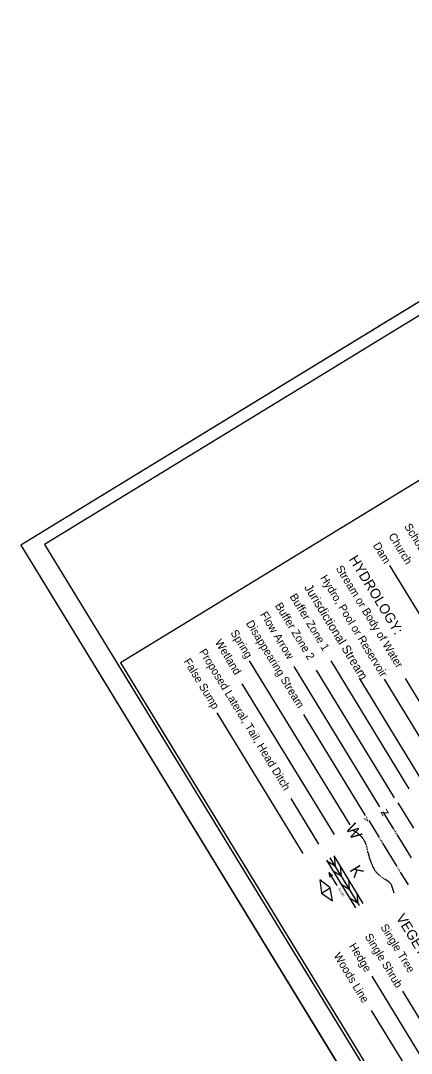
# Model space of a CAD drawing. Extents: x 1750583 to 1791140, y 783580 to 827376.
# Drawn here: x 1781915 to 1782342, y 784461 to 785591 of the extents above; entities that cross this region are included whole.
import ezdxf

# ---------------------------------------------------------------- set-up
doc = ezdxf.new("R2010")
doc.units = 0
for name, color, linetype in [('Sheet Cutting Line CELL', 7, 'Continuous'), ('Sheet Plot Border Inside CELL', 7, 'Continuous'), ('Sheet Plot Border Outside CELL', 7, 'Continuous'), ('Sheet Symbology CELL', 7, 'Continuous')]:
    doc.layers.add(name, color=color, linetype=linetype)

msp = doc.modelspace()

# ---------------------------------------------------------------- linework, layer by layer
at = {"layer": 'Sheet Cutting Line CELL'}
for p, q in [((1782853.7, 785590.6), (1781915.1, 785017.1)), ((1781915.1, 785017.1), (1782793.1, 783580.1))]:
    msp.add_line(p, q, dxfattribs=at)
at = {"layer": 'Sheet Plot Border Inside CELL'}
msp.add_lwpolyline([(1781941, 785017.7), (1782809.9, 783595.7), (1783710.2, 784145.8), (1782841.3, 785567.8)], close=True, dxfattribs=at)
at = {"layer": 'Sheet Plot Border Outside CELL'}
msp.add_lwpolyline([(1781915.1, 785017.1), (1782793.1, 783580.1), (1783731.7, 784153.6), (1782853.7, 785590.6)], close=True, dxfattribs=at)
at = {"layer": 'Sheet Symbology CELL'}
for p, q in [((1782436.3, 784802.2), (1782318.8, 784994.6)), ((1782275.2, 784711), (1782165.4, 784890.6)), ((1782339.9, 784750.5), (1782254.5, 784890.3)), ((1782307.7, 784730.9), (1782213.9, 784884.3)), ((1782323.8, 784740.7), (1782238.4, 784880.4)), ((1782258.1, 784700.6), (1782157.4, 784865.4)), ((1782354.1, 784759.2), (1782285.5, 784871.5)), ((1782373.4, 784771), (1782312.7, 784870.3)), ((1782390.4, 784781.4), (1782335.7, 784871)), ((1782224, 784679.7), (1782130, 784833.5)), ((1782292.2, 784721.4), (1782224.7, 784831.9)), ((1782241, 784690.1), (1782210.7, 784739.8)), ((1782327.5, 784735.3), (1782344.6, 784707.3)), ((1782311.1, 784725.3), (1782322.6, 784706.5)), ((1782295.6, 784715.9), (1782307.1, 784697.1)), ((1782307.6, 784696.2), (1782308.2, 784695.4)), ((1782323.1, 784705.7), (1782323.6, 784704.8)), ((1782324.1, 784704), (1782324.7, 784703.1)), ((1782325.2, 784702.2), (1782325.7, 784701.4)), ((1782326.2, 784700.5), (1782341.9, 784674.9)), ((1782293.8, 784684.3), (1782294, 784683.3)), ((1782308.7, 784694.5), (1782309.2, 784693.7)), ((1782309.7, 784692.8), (1782310.2, 784691.9)), ((1782310.8, 784691.1), (1782326.4, 784665.5)), ((1782249.3, 784672.4), (1782281.1, 784620.3)), ((1782253.1, 784675), (1782285.1, 784622.7)), ((1782257.4, 784677.3), (1782289.2, 784625.2)), ((1782257.9, 784676.5), (1782258.9, 784665.7)), ((1782258.9, 784665.7), (1782249.9, 784671.4)), ((1782264.5, 784665.7), (1782265.5, 784654.8)), ((1782326.9, 784664.6), (1782327.4, 784663.8)), ((1782328, 784662.9), (1782328.5, 784662.1)), ((1782329, 784661.2), (1782329.5, 784660.4)), ((1782253.5, 784642.1), (1782242, 784650.9)), ((1782242, 784650.9), (1782244.1, 784636.3)), ((1782252.1, 784659.1), (1782260.8, 784644.9)), ((1782252.1, 784659.1), (1782255.8, 784655.7)), ((1782252.1, 784659.1), (1782253, 784654)), ((1782265.5, 784654.8), (1782256.6, 784660.5)), ((1782273.3, 784651.2), (1782274.3, 784640.3)), ((1782308.1, 784655.3), (1782308.9, 784654.7)), ((1782309.7, 784654), (1782310.5, 784653.5)), ((1782330.1, 784659.5), (1782338.6, 784645.5)), ((1782244.1, 784636.3), (1782253.5, 784642.1)), ((1782255.8, 784627.8), (1782253.5, 784642.1)), ((1782274.3, 784640.3), (1782265.4, 784646)), ((1782244.1, 784636.3), (1782255.8, 784627.8)), ((1782283.5, 784625.4), (1782274.6, 784630.9)), ((1782282.6, 784636.1), (1782283.5, 784625.4)), ((1782410.2, 784364), (1782299.3, 784545.5)), ((1782427.3, 784374.5), (1782332.8, 784529)), ((1782393.1, 784353.6), (1782298.7, 784508.2))]:
    msp.add_line(p, q, dxfattribs=at)
msp.add_lwpolyline([(1783701.5, 784155.1), (1782919.5, 785435.1), (1782024.3, 784888.2), (1782806.4, 783608.2)], close=True, dxfattribs=at)
for points in [[(1782278.6, 784705.4), (1782281.1, 784703.6), (1782283.6, 784701.8), (1782284.2, 784701.4), (1782285.2, 784700.5), (1782285.9, 784699.8), (1782287, 784698.7), (1782288, 784697.6), (1782288.8, 784696.6), (1782289.4, 784695.7), (1782289.9, 784694.9), (1782290.4, 784694.2), (1782291.1, 784692.9), (1782291.6, 784691.9), (1782291.9, 784691.1), (1782292.3, 784689.9), (1782292.6, 784689.1)], [(1782292.9, 784688.1), (1782293, 784687.7), (1782293.1, 784687.2)], [(1782293.4, 784686.2), (1782293.5, 784685.8), (1782293.6, 784685.2)], [(1782294.2, 784682.3), (1782294.4, 784681.5), (1782294.8, 784680.1), (1782295.6, 784677.4), (1782296.2, 784675.4), (1782297.2, 784672.5), (1782298.2, 784669.5), (1782298.9, 784667.9), (1782299.4, 784666.5), (1782300, 784665.3), (1782300.5, 784664.3), (1782301, 784663.4), (1782301.5, 784662.6), (1782302.3, 784661.3), (1782303, 784660.3), (1782303.5, 784659.6), (1782304.3, 784658.6), (1782305.2, 784657.7), (1782306, 784657), (1782306.6, 784656.4), (1782307.3, 784655.9)], [(1782311.3, 784652.9), (1782311.5, 784652.8), (1782312.1, 784652.3)], [(1782313, 784651.8), (1782313.4, 784651.5), (1782315.3, 784650.4), (1782316.3, 784649.8), (1782317.2, 784649.1), (1782317.8, 784648.6), (1782318.3, 784648.1), (1782318.8, 784647.6), (1782319.1, 784647.2), (1782319.7, 784646.4), (1782320.1, 784645.8), (1782320.3, 784645.3), (1782320.6, 784644.5), (1782320.9, 784643.8), (1782321.9, 784640.2), (1782322.9, 784636.7)]]:
    msp.add_lwpolyline(points, dxfattribs=at)

# ---------------------------------------------------------------- texts
for s, height, rotation, p in [('School', 8.75, 301.4249, (1782334.1, 785037.6)), ('Church', 8.75, 301.4249, (1782316.8, 785027.1)), ('Dam', 8.75, 301.4249, (1782299.9, 785016.8)), ('HYDROLOGY:', 11, 301.4249, (1782273.5, 785001.6)), ('Stream or Body of Water', 8.75, 301.4249, (1782259.3, 784991.6)), ('Hydro, Pool or Reservoir', 8.75, 301.4249, (1782242.3, 784981.2)), ('Jurisdictional Stream', 9.646, 301.4249, (1782224.6, 784970.8)), ('Buffer Zone 2', 8.75, 301.4249, (1782192.7, 784950.9)), ('Buffer Zone 1', 8.75, 301.4249, (1782208.8, 784960.8)), ('Flow Arrow', 8.75, 301.4249, (1782176.6, 784941.1)), ('Disappearing Stream', 8.75, 301.4249, (1782161.1, 784931.6)), ('Spring', 8.75, 301.4249, (1782144.1, 784921.2)), ('Wetland', 8.75, 301.4249, (1782127, 784910.8)), ('Proposed Lateral, Tail, Head Ditch', 8.75, 301.4249, (1782109.9, 784900.4)), ('False Sump', 8.75, 301.4249, (1782092.9, 784889.9)), ('z', 10, 121.425, (1782318, 784723.6)), ('v', 6.6, 31.1841, (1782292.4, 784713.9)), ('W', 12.8, 301.4249, (1782269.8, 784707.5)), ('K', 12.8, 301.4249, (1782274.2, 784661.9)), ('FLOW', 2.59, 301.4249, (1782261.7, 784640.9)), ('VEGETATION:', 11, 301.4249, (1782325.1, 784609.6)), ('Single Tree', 8.75, 301.4249, (1782308, 784599.4)), ('Hedge', 8.75, 301.4249, (1782273.8, 784578.6)), ('Single Shrub', 8.75, 301.4249, (1782290.9, 784589)), ('Woods Line', 8.75, 301.4249, (1782256.8, 784568.1))]:
    msp.add_text(s, height=height, rotation=rotation, dxfattribs=at).set_placement(p)

doc.saveas('drawing.dxf')
